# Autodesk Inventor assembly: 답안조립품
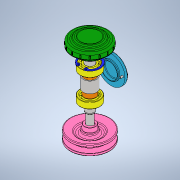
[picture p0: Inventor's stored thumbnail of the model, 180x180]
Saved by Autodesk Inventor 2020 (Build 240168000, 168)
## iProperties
Created: 2022-05
Part Number: 답안조립품
Document SubType Name: Assembly
Designer: Student
Author: Student
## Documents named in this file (17)
- C:\Users\Student\Desktop\720506V1021\답안조립품.iam
- C:\Users\Student\Desktop\720506V1021\부품.ipt
- C:\Users\Student\Desktop\720506V1021\십자볼트 M3 x 10.ipt
- C:\Users\Student\Desktop\720506V1021\와셔 3 x 6.ipt
- C:\Users\Student\Desktop\720506V1021\탑 커버.ipt
- C:\Users\Student\Desktop\720506V1021\사이드 커버.ipt
- 사이드 커버.ipt
- C:\Users\Student\Desktop\720506V1021\개스킷.ipt
- C:\Users\Student\Desktop\720506V1021\축.ipt
- C:\Users\Student\Desktop\720506V1021\V-벨트풀리.ipt
- C:\Users\Student\Desktop\720506V1021\볼트 M4 x 10.ipt
- C:\Users\Student\Desktop\720506V1021\와셔 4 x 16.ipt
- C:\Users\Student\Desktop\720506V1021\키 4 x 4.ipt
- C:\Users\Student\Desktop\720506V1021\부시1.ipt
- C:\Users\Student\Desktop\720506V1021\베어링 6202.ipt
- C:\Users\Student\Desktop\720506V1021\멈춤링 15 x 1.ipt
- C:\Users\Student\Desktop\720506V1021\멈춤링 35 x 1.6.ipt
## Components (3 placed, 3 different names)
1. 개스킷:1
2. V-벨트풀리:1
3. ISO 4017 M4 x 10:1
